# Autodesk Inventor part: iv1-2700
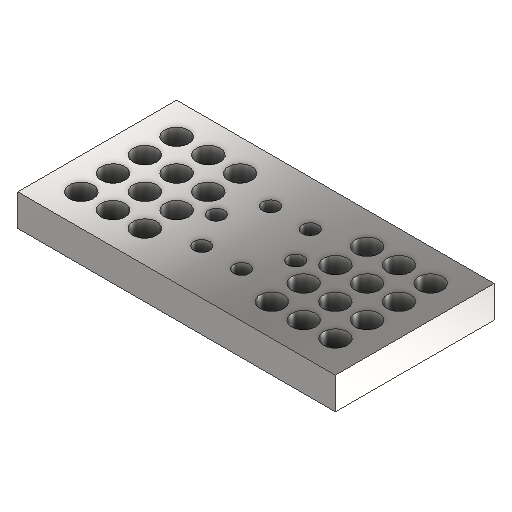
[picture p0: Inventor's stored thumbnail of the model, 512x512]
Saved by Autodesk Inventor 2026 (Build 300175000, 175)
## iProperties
Created: 2022-01
Part Number: iv1-2700
Material: Steel, Mild
Document SubType Name: Modeling
Designer: Lars Bertram Pedersen
Density: 7.85 g/cm^3
Appearance: Semi-Polished
Author: Lars Bertram Pedersen
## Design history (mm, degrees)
sketch "Sketch1"
  geometry: L1 (-100, -50)-(100, -50); L2 (100, -50)-(100, 50); L3 (100, 50)-(-100, 50); L4 (-100, 50)-(-100, -50); L5 (-100, 50)-(100, -50); 2 further points
  constraints: 10 end point, 2 parallel, 1 coincident, 1 horizontal, 1 midpoint, 1 perpendicular
  dimensions: "d0" = 200 distance of L2.end L3.end; "d1" = 100 distance of L3.end L1.start
extrude "Extrusion1" new body sketch "Sketch1" distance "d2" = 20; taper "d3" = 0 deg
sketch "Sketch2"
  geometry: L1 (-100, 50)-(0, 0) reference; L2 (0, 0)-(100, -50) reference; 1 further point
  dimensions: "d4" = 20 distance from line of L1 point (-80, -30); "d5" = 20 distance from line of L2 point (-80, -30)
hole "Hole1" sketch "Sketch2" diameter "d6" = 15; stored, may be unused: countersink angle "d10" = 90 deg, drill point angle "d12" = 118 deg; dims "d7" = 6, "d8" = 4, "d9" = 2, "d11" = 8
pattern_linear "Rectangular Pattern1" dims "d18" = 20
sketch "Sketch3"
  geometry: L1 (100, -50)-(100, 50) reference; L2 (0, 0)-(100, -50) reference; 1 further point
  dimensions: "d19" = 20 distance from line of L1 point (80, -30); "d20" = 20 distance from line of L2 point (80, -30)
hole "Hole2" sketch "Sketch3" diameter "d21" = 15; stored, may be unused: countersink angle "d25" = 90 deg, drill point angle "d27" = 118 deg; dims "d22" = 6, "d23" = 4, "d24" = 2, "d26" = 8
pattern_linear "Rectangular Pattern2" dims "d33" = 20
sketch "Sketch5"
  geometry: L1 (100, 50)-(-100, 50) reference; L2 (-100, 50)-(-100, -50) reference; 2 further points
  dimensions: "d49" = 50 distance from line of L1 point (-25, 0); "d50" = 75 distance from line of L2 point (-25, 0)
hole "Hole4" sketch "Sketch5" diameter "d51" = 10; stored, may be unused: countersink angle "d55" = 90 deg, drill point angle "d57" = 118 deg; dims "d52" = 6, "d53" = 4, "d54" = 2, "d56" = 8
pattern_circular "Circular Pattern1" dims angle "d59" = 360 deg
body "Solid1"
